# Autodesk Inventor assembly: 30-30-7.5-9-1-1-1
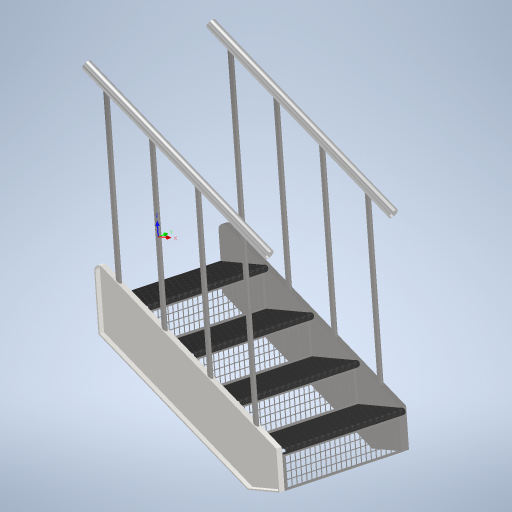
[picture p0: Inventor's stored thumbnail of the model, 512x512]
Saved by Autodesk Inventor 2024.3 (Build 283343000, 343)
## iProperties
RuleStatus: InUse
Company: Elevation Stair Company
Created: 2022-06
Part Number: 30-30-7.5-9-1-1-1
Document SubType Name: Assembly
Designer: David Reaume
Description: Metal Stairs
AfterAnyUserParamChange0: Type Name
Run: 9.000 in
TheAngle: 39.81 deg
TargetRise: 7.250 in
Rise: 7.500 in
Height: 30.000 in
Width: 30.000 in
StringerWidth: 10.000 in
StringerThickness: 1.500 in
StringerLength: 46.861 in
NumberOfSteps: 5.000 ul
Length: 36.000 in
TreadThickness: 1.250 in
StringerStockLength: 48.000 in
RailingStockLength: 46.861 in
RailingWidth: 3.000 in
RailingThickness: 2.000 in
RightRail: True
LeftRail: True
StringerMaterial: Steel, Galvanized
TreadMaterial: Steel, Wrought
RiserMaterial: Steel, Galvanized
BalusterMaterial: Steel, Galvanized
HandrailMaterial: Aluminum 6061
HasHandrail: True
HasRiser: True
BalusterLength: 36.000 in
BalusterDia: 1.000 in
INDDataset: sample
Author: David Reaume
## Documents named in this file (13)
- C:\Users\partonj\Desktop\JP\Inventor Datasets\IND Samples (Analytics ID Added)\Inventor 2024\Staircase Sample1\Staircase Sample\Staircase Sample.iam
- C:\Users\partonj\Desktop\JP\Inventor Datasets\IND Samples (Analytics ID Added)\Inventor 2024\Staircase Sample1\Staircase Sample\Stringer.ipt
- C:\Users\partonj\Desktop\JP\Inventor Datasets\IND Samples (Analytics ID Added)\Inventor 2024\Staircase Sample1\Staircase Sample\Tread.ipt
- C:\Users\partonj\Desktop\JP\Inventor Datasets\IND Samples (Analytics ID Added)\Inventor 2024\Staircase Sample1\Staircase Sample\Riser.ipt
- C:\Users\partonj\Desktop\JP\Inventor Datasets\IND Samples (Analytics ID Added)\Inventor 2024\Staircase Sample1\Staircase Sample\Baluster.ipt
- C:\Users\partonj\Desktop\JP\Inventor Datasets\IND Samples (Analytics ID Added)\Inventor 2024\Staircase Sample1\Staircase Sample\Railing.ipt
- C:\Users\partonj\Desktop\JP\Inventor Datasets\IND Samples (Analytics ID Added)\Inventor 2024\Staircase Sample1\Staircase Sample\Left Stringer_MIR.ipt
- D:\MID Staircase\Stringer.ipt
- D:\MID Staircase\Tread.ipt
- D:\MID Staircase\Riser.ipt
- D:\MID Staircase\Baluster.ipt
- D:\MID Staircase\Railing.ipt
- D:\MID Staircase\Left Stringer_MIR.ipt
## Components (20 placed, 7 different names)
1. Stringer
2. Left Stringer_MIR:1
3. Right Railing
4. Left Railing — Flush:7, Flush:8, Flush:9
5. Tread:1
6. Tread:2
7. Tread:3
8. Tread:4
9. Riser:1
10. Riser:2
11. Riser:3
12. Riser:4
13. Baluster:1
14. Baluster:12
15. Baluster:15
16. Baluster:17
17. Baluster:7 — Flush:11, Flush:12
18. Baluster:8
19. Baluster:13
20. Baluster:16
## Component patterns: Tread Pattern (4 elements), Riser Pattern (4 elements), Right Baluster Pattern (4 elements), Left Baluster Pattern (4 elements)
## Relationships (5: Flush 5)
- Flush:7: Left Railing
- Flush:8: Left Railing
- Flush:9: Left Railing
- Flush:11: Baluster:7
- Flush:12: Baluster:7
## Named parameters: TheAngle = 6.94738 mm, StringerThickness = 38.1 mm, StringerLength = 1190.28205 mm, Length = 914.4 mm, TheAngleRounded = 6.94816 mm, StringerStockLength = 1219.2 mm, DiagonalTreadSpacing = 297.57051 mm, BalusterDia = 25.4 mm, BalusterLength = 914.4 mm, RailingStockLength = 1190.28205 mm, RailingWidth = 76.2 mm, RailingThickness = 50.8 mm, StringerSpacing = 876.3 mm
